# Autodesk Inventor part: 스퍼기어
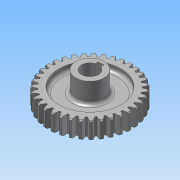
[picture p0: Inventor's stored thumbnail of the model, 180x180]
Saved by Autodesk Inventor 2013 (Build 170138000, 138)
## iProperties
Created: 2013-08
Part Number: 스퍼기어
Material: 강
Document SubType Name: Modeling
Designer: 한국산업디자인학원
Categories: <?xml version="1.0" encoding="UTF-16"?> <MemberInstance><Categories><FamilyTemplate><FamilyTemplateParameter ValueType="xs:double" Id="1" ObjectReferenceKey="da
Density: 1 g/cm^3
CustomPartVersion: 1
Author: 한국산업디자인학원
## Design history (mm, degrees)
sketch "Sketch1"
  geometry: C1 r 37 at (0, 0)
  constraints: 1 centre point
  dimensions: "d0" = 74 diameter of C1 (= da_da)
extrude "Extrusion1" new body sketch "Sketch1" distance "d1" = 15 (= da_b); taper "d2" = 0 deg
chamfer "모따기1" distance "d49" = 1; stored, may be unused: second distance "d50" = 2, angle "d51" = 45 deg
workplane "Work Plane2"
feature "피치 지름" dims "d4" = 10, "d5" = 0
workplane "Work Plane8"
workplane "Work Plane9"
feature "스퍼 기어" dims "da_b" = 15, "da_d" = 70, "da_aw" = 70, "da_da" = 74, "da_df" = 65, "da_dw" = 70, angle "da_beta" = 0 deg, "da_lefttooth" = 0, "da_righttooth" = 0
sketch "스케치3"
  geometry: C1 r 27.5 at (0, 0); A1 r 36 centre (0, 0) between (-5.215, 35.62) and (-7.633, 35.181) reference
  constraints: 1 centre point, 1 coincident
  dimensions: "d52" = 55 diameter of C1
extrude "돌출2" cut sketch "스케치3" distance "d54" = 5; taper "d55" = 0 deg
sketch "스케치4"
  geometry: C1 r 27.5 at (0, 0) reference
extrude "돌출3" cut sketch "스케치4" distance "d56" = 5; taper "d57" = 0 deg
sketch "스케치5"
  geometry: C1 r 27.5 at (0, 0) reference; C2 r 12.5 at (0, 0)
  constraints: 1 centre point, 1 coincident
  dimensions: "d58" = 25 diameter of C2
extrude "돌출4" join sketch "스케치5" distance "d60" = 8; taper "d61" = 0 deg
sketch "스케치6"
  geometry: C1 r 27.5 at (0, 0) reference; C2 r 12.5 at (0, 0)
  constraints: 1 centre point, 1 coincident
  dimensions: "d62" = 25 diameter of C2
extrude "돌출5" join sketch "스케치6" distance "d64" = 18; taper "d65" = 0 deg
hole "구멍1" diameter "d68" = 15; stored, may be unused: countersink angle "d72" = 90 deg, drill point angle "d74" = 118 deg; dims "d66" = 10, "d67" = 10, "d69" = 6, "d70" = 4, "d71" = 2, "d73" = 8
sketch "스케치7"
  geometry: L1 (-2.5, 7.071)-(-2.5, 9.8); L2 (-2.5, 9.8)-(2.5, 9.8); L3 (2.5, 9.8)-(2.5, 7.071); C1 r 12.5 at (0, 0) reference; A1 r 7.5 centre (0, 0) between (-2.5, 7.071) and (2.5, 7.071) reference
  constraints: 6 end point, 2 parallel, 2 point on circle, 1 perpendicular, 1 vertical
  dimensions: "d75" = 5 distance of L1.end L2.end; "d77" = 17.3 dimension on A1 L2
fillet "모깎기1" dims "d78" = 3
sketch "스케치8"
  geometry: L1 (-2.5, 7.071)-(-2.5, 9.8); L2 (-2.5, 9.8)-(2.5, 9.8); L3 (2.5, 9.8)-(2.5, 7.071); A1 r 7.5 centre (0, 0) between (-2.5, 7.071) and (2.5, 7.071) reference
  constraints: 6 end point, 2 parallel, 2 point on circle, 1 perpendicular, 1 vertical
  dimensions: "d79" = 5 distance of L1.end L2.end; "d81" = 17.3 dimension on A1 L2
extrude "돌출6" cut sketch "스케치8" stored distance "d82" = 10; taper "d83" = 0 deg
body "Solid1"
sketch "Sketch2"
  geometry: C1 r 37 at (0, 0) reference; C2 r 35 at (0, 0)
  constraints: 1 centre point, 1 coincident
  dimensions: "d3" = 70 diameter of C2 (= da_dw)
body "Srf1"
other parameters: "d17" = 0, "d34" = 0.8976 (computed from da_z), "d39" = 0, "d41" = 0, "d47" = 0, "d48" = 0
